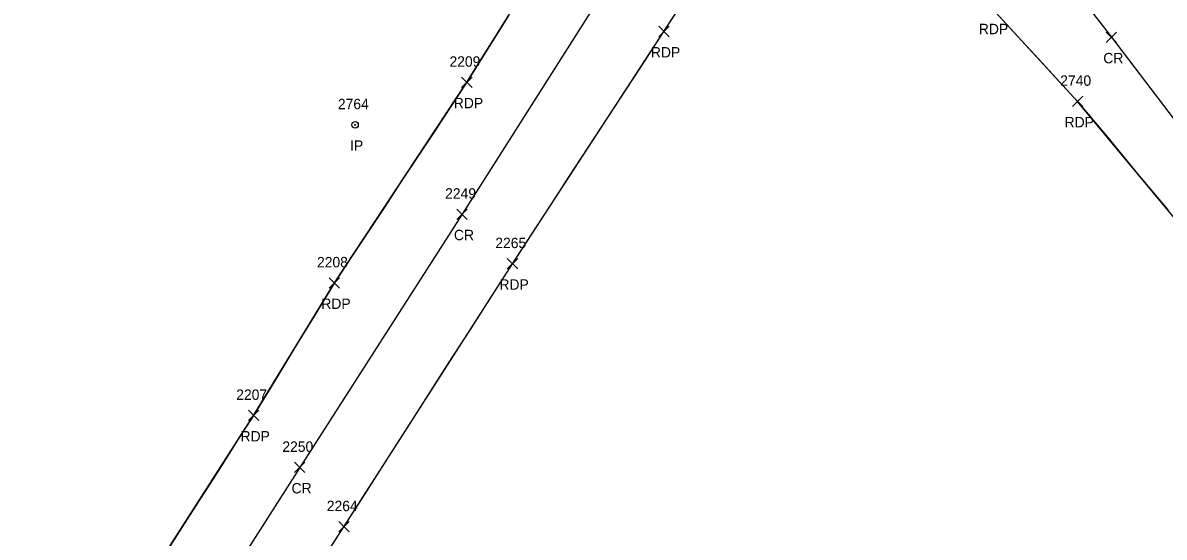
# Model space of a CAD drawing. Extents: x 1638344 to 1639591, y 610835 to 612202.
# Drawn here: x 1638979.2 to 1639198.8, y 611110.3 to 611209.2 of the extents above; entities that cross this region are included whole.
import ezdxf

# ---------------------------------------------------------------- set-up
doc = ezdxf.new("R2010")
doc.units = 0
for name, color, linetype in [('LSOGP', 7, 'Continuous'), ('M_A', 7, 'Continuous'), ('M_I', 7, 'Continuous'), ('MPIR', 7, 'Continuous'), ('P_A', 7, 'Continuous'), ('P_I', 7, 'Continuous'), ('P_TIC', 7, 'Continuous'), ('PET', 7, 'Continuous'), ('PRC', 7, 'Continuous')]:
    doc.layers.add(name, color=color, linetype=linetype)

msp = doc.modelspace()

# ---------------------------------------------------------------- linework, layer by layer
at = {"layer": 'LSOGP'}
for points in [[(1639036.38, 611105.17), (1639040.97, 611112.29), (1639045.02, 611118.61), (1639049.08, 611124.94), (1639053.13, 611131.26), (1639057.19, 611137.59), (1639061.24, 611143.92), (1639065.3, 611150.24), (1639069.35, 611156.57), (1639073.41, 611162.89), (1639077.05, 611168.48), (1639080.7, 611174.06), (1639084.34, 611179.64), (1639087.99, 611185.23), (1639091.63, 611190.81), (1639095.28, 611196.39), (1639098.92, 611201.98), (1639102.56, 611207.56), (1639107.99, 611215.92)], [(1639165.68, 611212.04), (1639169.81, 611207.56), (1639173.94, 611203.08), (1639178.06, 611198.6), (1639182.19, 611194.12), (1639187.97, 611187.16), (1639193.74, 611180.2), (1639199.52, 611173.24)], [(1639072.57, 611210.54), (1639068.59, 611204.17), (1639064.62, 611197.79), (1639061.43, 611192.96), (1639058.25, 611188.14), (1639055.06, 611183.31), (1639051.87, 611178.49), (1639048.68, 611173.66), (1639045.49, 611168.84), (1639042.31, 611164.01), (1639039.12, 611159.19), (1639035.23, 611152.82), (1639031.34, 611146.44), (1639027.46, 611140.07), (1639023.57, 611133.7), (1639020.63, 611129.11), (1639017.69, 611124.52), (1639014.75, 611119.92), (1639011.81, 611115.33), (1639008.86, 611110.74), (1639005.92, 611106.15)]]:
    msp.add_lwpolyline(points, dxfattribs=at)
at = {"layer": 'MPIR'}
for radius in [0.625, 0.0833]:
    msp.add_circle((1639043.11, 611189.61), radius, dxfattribs=at)
at = {"layer": 'P_TIC'}
for points in [[(1639101.57, 611206.56), (1639103.56, 611208.56)], [(1639103.56, 611206.56), (1639101.57, 611208.56)], [(1639187.7, 611205.44), (1639189.7, 611207.44)], [(1639189.7, 611205.44), (1639187.7, 611207.44)], [(1639063.62, 611196.79), (1639065.62, 611198.79)], [(1639065.62, 611196.79), (1639063.62, 611198.79)], [(1639181.19, 611193.12), (1639183.19, 611195.12)], [(1639183.19, 611193.12), (1639181.19, 611195.12)], [(1639062.71, 611171.41), (1639064.71, 611173.41)], [(1639064.71, 611171.41), (1639062.71, 611173.41)], [(1639072.41, 611161.89), (1639074.41, 611163.89)], [(1639074.41, 611161.89), (1639072.41, 611163.89)], [(1639038.12, 611158.19), (1639040.12, 611160.19)], [(1639040.12, 611158.19), (1639038.12, 611160.19)], [(1639022.57, 611132.7), (1639024.57, 611134.7)], [(1639024.57, 611132.7), (1639022.57, 611134.7)], [(1639031.46, 611122.7), (1639033.46, 611124.7)], [(1639033.46, 611122.7), (1639031.46, 611124.7)], [(1639039.97, 611111.29), (1639041.97, 611113.29)], [(1639041.97, 611111.29), (1639039.97, 611113.29)]]:
    msp.add_lwpolyline(points, dxfattribs=at)
at = {"layer": 'PET'}
for points in [[(1638854.83, 610853.22), (1638885.37, 610909), (1638902.82, 610937.28), (1638929.33, 610982.56), (1638950.92, 611019.42), (1638971.29, 611051.92), (1639000.04, 611096.97), (1639023.57, 611133.7), (1639039.12, 611159.19), (1639064.62, 611197.79), (1639080.51, 611223.3), (1639114.23, 611277.34), (1639131.17, 611302.28), (1639149.64, 611331.79), (1639176.42, 611372.36), (1639193.48, 611398.88)], [(1638878.4, 610839.82), (1638902.26, 610883.1), (1638925.76, 610925.07), (1638957.26, 610978.12), (1638978.73, 611014.12), (1639004.29, 611055.33), (1639040.97, 611112.29), (1639073.41, 611162.89), (1639102.56, 611207.56), (1639124.27, 611240.99), (1639140.69, 611264.29), (1639156.2, 611287.4), (1639175.63, 611318.1), (1639189.77, 611341.61), (1639219.88, 611389.38)], [(1639410.83, 610892.36), (1639390.46, 610919.54), (1639371.81, 610946.36), (1639349.88, 610975.69), (1639327.19, 611005.39), (1639302.76, 611038.38), (1639275.03, 611075.51), (1639248.84, 611108.82), (1639223.63, 611142.45), (1639205.3, 611166.28), (1639182.19, 611194.12), (1639165.68, 611212.04), (1639150.22, 611225.99), (1639136.41, 611234.04), (1639135.29, 611232.53), (1639130.93, 611235.27), (1639127.56, 611237.67), (1639124.14, 611238.64)]]:
    msp.add_lwpolyline(points, dxfattribs=at)
at = {"layer": 'PRC'}
for points in [[(1639222.36, 611418.19), (1639195.34, 611376.27), (1639169.71, 611336.75), (1639147.17, 611302.78), (1639120.59, 611261.17), (1639092.55, 611217.83), (1639063.71, 611172.41), (1639032.46, 611123.7), (1639004.79, 611080.3), (1638977.88, 611037.27), (1638950.44, 610992.13), (1638925.95, 610950.29), (1638900.28, 610905.37), (1638879.75, 610869.2), (1638867.14, 610846.08)], [(1639145.03, 611260.3), (1639159.75, 611243.63), (1639188.7, 611206.44), (1639218.55, 611167.29), (1639245.48, 611130.83), (1639271.83, 611094.92), (1639293.45, 611066.85), (1639319.08, 611033.06), (1639349.49, 610993.07), (1639374.15, 610959.6), (1639396.77, 610928.59), (1639419.08, 610897.87)]]:
    msp.add_lwpolyline(points, dxfattribs=at)

# ---------------------------------------------------------------- texts
at = {"layer": 'M_A'}
msp.add_text('IP', height=2, dxfattribs=at).set_placement((1639042.15, 611184.61))
at = {"layer": 'M_I'}
msp.add_text('2764', height=2, dxfattribs=at).set_placement((1639039.8, 611192.61))
at = {"layer": 'P_A'}
for s, p in [('RDP', (1639163.17, 611207.04)), ('RDP', (1639100.05, 611202.56)), ('CR', (1639187.13, 611201.44)), ('RDP', (1639062.11, 611192.79)), ('RDP', (1639179.68, 611189.12)), ('CR', (1639062.14, 611167.41)), ('RDP', (1639070.89, 611157.89)), ('RDP', (1639036.61, 611154.19)), ('RDP', (1639021.06, 611128.7)), ('CR', (1639030.89, 611118.7))]:
    msp.add_text(s, height=2, dxfattribs=at).set_placement(p)
at = {"layer": 'P_I'}
for s, p in [('2209', (1639061.28, 611200.79)), ('2740', (1639178.84, 611197.12)), ('2249', (1639060.44, 611175.41)), ('2265', (1639070.1, 611165.89)), ('2208', (1639035.78, 611162.19)), ('2207', (1639020.23, 611136.7)), ('2250', (1639029.11, 611126.7)), ('2264', (1639037.66, 611115.29))]:
    msp.add_text(s, height=2, dxfattribs=at).set_placement(p)

doc.saveas('drawing.dxf')
